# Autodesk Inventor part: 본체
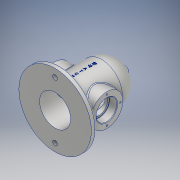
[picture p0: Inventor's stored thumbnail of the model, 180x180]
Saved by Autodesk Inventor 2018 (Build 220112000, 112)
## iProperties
Created: 2019-11
Part Number: 본체
Material: 알루미늄 6061
Document SubType Name: Modeling
Designer: Administrator
Density: 2.7 g/cm^3
Appearance: 알루미늄 - 평지
Mass: 1105.83 g
Surface Area: 883.522 cm^2
Volume: 409.568 cm^3
Author: Administrator
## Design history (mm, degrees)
sketch "스케치1"
  geometry: C1 r 70 at (0, 0); 1 further point
  constraints: 1 centre point, 1 coincident
  dimensions: "d0" = 140 diameter of C1
extrude "돌출1" new body sketch "스케치1" distance "d1" = 10; taper "d2" = 0 deg
sketch "스케치2"
  geometry: C1 r 40 at (0, 0); 1 further point
  constraints: 1 centre point, 1 coincident
  dimensions: "d3" = 80 diameter of C1
extrude "돌출2" join sketch "스케치2" distance "d4" = 80; taper "d5" = 0 deg
sketch "스케치4"
  geometry: L1 (40, 90)-(-40, 90) reference; L2 (-40, 90)-(0, 90); L3 (0, 130)-(0, 90); A1 r 40 centre (0, 90) between (0, 130) and (-40, 90); 1 further point
  constraints: 4 end point, 2 point on circle, 1 centre point, 1 collinear, 1 midpoint, 1 vertical
revolve "회전1" sketch "스케치4" stored, may be unused: angle "d6" = 360 deg
sketch "스케치5"
  geometry: C1 r 30 at (0, 0); 1 further point
  constraints: 1 centre point, 1 coincident
  dimensions: "d7" = 60 diameter of C1
extrude "돌출3" cut sketch "스케치5" distance "d8" = 90; taper "d9" = 0 deg
sketch "스케치6"
  geometry: L1 (30, 90)-(-30, 90) reference; L2 (-30, 90)-(0, 90); L3 (0, 90)-(0, 120); A1 r 30 centre (0, 90) between (0, 120) and (-30, 90); 1 further point
  constraints: 4 end point, 2 point on circle, 1 centre point, 1 collinear, 1 midpoint, 1 vertical
revolve "회전2" sketch "스케치6" stored, may be unused: angle "d10" = 360 deg
sketch "스케치7"
  geometry: C1 r 31 at (50, 0); 1 further point
  constraints: 1 centre point
  dimensions: "d12" = 62 diameter of C1
extrude "돌출4" join sketch "스케치7" stored distance "d13" = 100; taper "d14" = 0 deg
sketch "스케치8"
  geometry: C1 r 30 at (0, 0); 1 further point
  constraints: 1 centre point, 1 coincident
extrude "돌출5" cut sketch "스케치8" distance "d15" = 90; taper "d16" = 0 deg
sketch "스케치9"
  geometry: C1 r 20 at (0, 0); 1 further point
  constraints: 1 centre point
  dimensions: "d17" = 40 diameter of C1
extrude "돌출6" cut sketch "스케치9" distance "d18" = 15; taper "d19" = 0 deg
sketch "스케치10"
  geometry: C1 r 20 at (0, 0); 1 further point
  constraints: 1 centre point
  dimensions: "d20" = 40 diameter of C1
extrude "돌출7" cut sketch "스케치10" distance "d21" = 15; taper "d22" = 0 deg
sketch "스케치11"
  geometry: C1 r 16.5 at (0, 0); 1 further point
  constraints: 1 centre point
  dimensions: "d23" = 33 diameter of C1
extrude "돌출8" cut sketch "스케치11" extent not by distance; stored distance "d24" = 15; taper "d25" = 0 deg
fillet "모깎기1" dims "d26" = 0.3
sketch "스케치13"
  geometry: C1 r 7.5 at (0, 0); 1 further point
  constraints: 1 centre point, 1 coincident
  dimensions: "d27" = 15 diameter of C1
extrude "돌출9" join sketch "스케치13" distance "d28" = 135; taper "d29" = 0 deg
sketch "스케치14"
  geometry: C1 r 7.5 at (0, 0); 1 further point
  constraints: 1 centre point, 1 coincident
extrude "돌출10" cut sketch "스케치14" distance "d30" = 90; taper "d31" = 0 deg
sketch "스케치15"
  geometry: L1 (30, 90)-(-30, 90) reference; L2 (-30, 90)-(0, 90); L3 (7.5, 90)-(-7.5, 90) reference; L4 (7.5, 119.047)-(-7.5, 119.047) reference; L5 (0, 120)-(0, 90); A1 r 30 centre (0, 90) between (0, 120) and (-30, 90); 1 further point
  constraints: 5 end point, 2 point on circle, 1 centre point, 1 collinear, 1 midpoint, 1 perpendicular
revolve "회전3" sketch "스케치15" stored, may be unused: angle "d32" = 360 deg
sketch "스케치16"
  geometry: 1 further point
sketch "스케치17"
  geometry: C1 r 7.5 at (0, 0) reference; C2 r 3 at (0, 0); 1 further point
  constraints: 1 centre point, 1 coincident
  dimensions: "d33" = 6 diameter of C2
extrude "돌출11" cut sketch "스케치17" distance "d34" = 90; taper "d35" = 0 deg
feature "스레드1" dims "d36" = 10, "d37" = 0
sketch "스케치18"
  geometry: 5 further points
hole "구멍1" sketch "스케치18" at (0, 26), (-26, 0), (0, -26), (26, 0) diameter "d39" = 3.242; stored, may be unused: countersink angle "d43" = 90 deg, drill point angle "d45" = 118 deg; dims "d40" = 8, "d41" = 4, "d42" = 2, "d44" = 10
fillet "모깎기2" dims "d46" = 3
sketch "스케치19"
  geometry: C1 r 4.5 at (0, 55); C2 r 4.5 at (0, -55); A1 r 55 centre (0, 0) between (0, 55) and (0, -55); 1 further point
  constraints: 3 centre point, 2 point on circle, 1 coincident
  dimensions: "d47" = 110 diameter of A1; "d48" = 9 diameter of C1; "d49" = 9 diameter of C2
extrude "돌출12" cut sketch "스케치19" distance "d50" = 90; taper "d51" = 0 deg
fillet "모깎기3" dims "d52" = 3
node "작업 평면2"
sketch "스케치24"
  geometry: L1 (-40, 13)-(40, 13); L2 (30, 90)-(-30, 90); L3 (-70, 0)-(70, 0); 2 further points
  constraints: 6 end point, 1 other
feature "엠보싱1" sketch "스케치24" dims "d2" = 0, "d8" = 90, "d9" = 0, "d60" = 0.5, "d61" = 0
chamfer "모따기1" distance "d62" = 1; stored, may be unused: second distance "d63" = 2, angle "d64" = 45 deg
node "솔리드1"
mirror "미러1"
